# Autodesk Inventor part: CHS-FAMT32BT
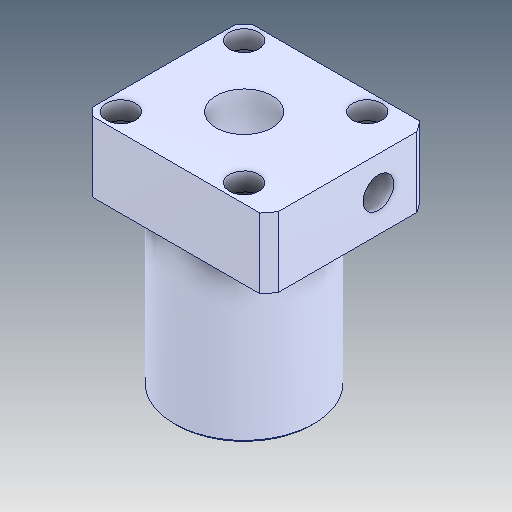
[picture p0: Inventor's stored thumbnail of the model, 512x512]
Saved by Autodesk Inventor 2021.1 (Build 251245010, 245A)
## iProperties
Created: 2021-05
Part Number: CHS-FAMT32BT
Material: Ogólny
Document SubType Name: Modeling
Designer: user
Density: 1 g/cm^3
Appearance: Domyślna
Author: user
Revision Number: ÈÎºÎ
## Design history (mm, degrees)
feature "Í¹Ì¨-À­Éì1"
node "Bryła1"
